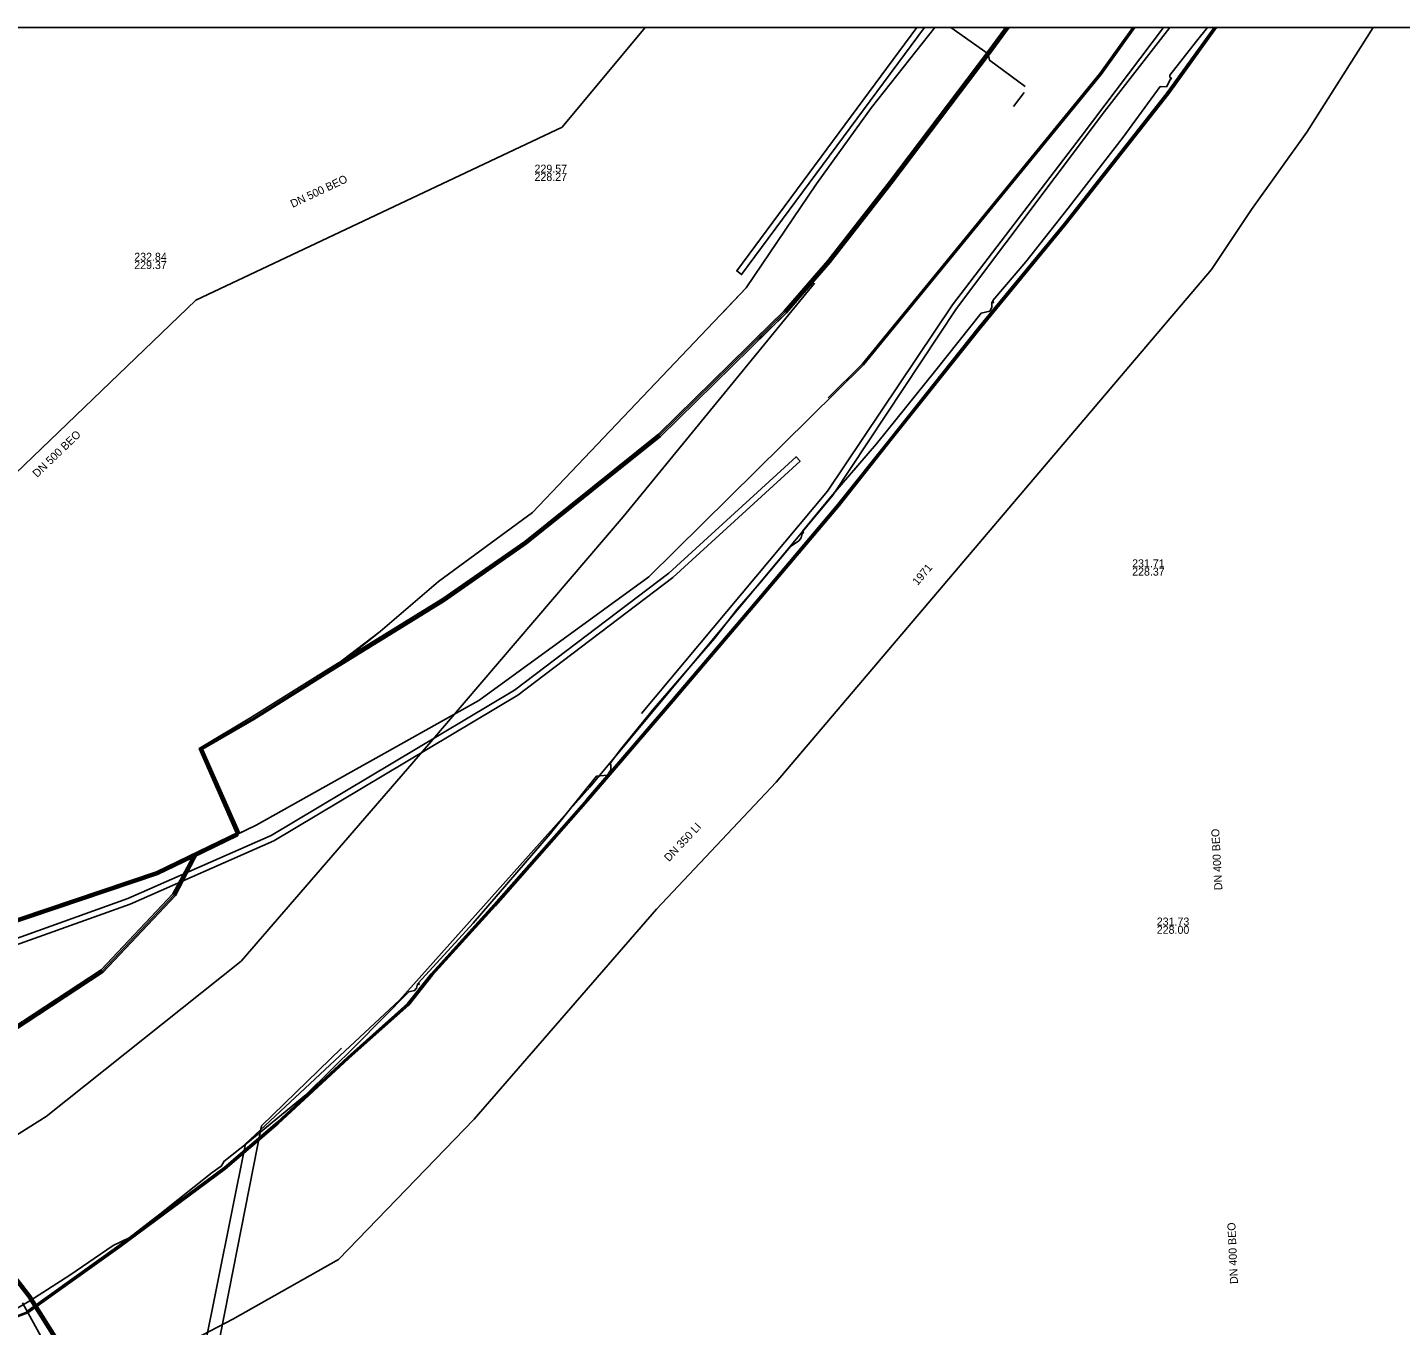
# Model space of a CAD drawing. Extents: x -599951 to -598963, y -1164095 to -1162939.
# Drawn here: x -599594.4 to -599456.3, y -1163069.9 to -1162939.4 of the extents above; entities that cross this region are included whole.
import ezdxf

# ---------------------------------------------------------------- set-up
doc = ezdxf.new("R2010")
doc.units = 0
for name, color, linetype in [('Level 3', 7, 'Continuous'), ('Vrstva 12', 7, 'Continuous'), ('Vrstva 13', 7, 'Continuous'), ('Vrstva 15', 7, 'Continuous'), ('Vrstva 20', 7, 'Continuous'), ('Vrstva 3', 7, 'Continuous'), ('Vrstva 42', 7, 'Continuous'), ('Vrstva 50', 7, 'Continuous'), ('Vrstva 53', 7, 'Continuous'), ('Vrstva 55', 7, 'Continuous'), ('Vrstva 58', 7, 'Continuous'), ('Vrstva 9', 7, 'Continuous')]:
    doc.layers.add(name, color=color, linetype=linetype)

msp = doc.modelspace()

# ---------------------------------------------------------------- linework, layer by layer
at = {"layer": 'Level 3'}
msp.add_lwpolyline([(-599584.11, -1163027.52), (-599598.37, -1163032.64), (-599613.87, -1163036.89), (-599614.07, -1163036.32), (-599598.55, -1163032.06), (-599584.33, -1163026.96), (-599569.91, -1163020.64), (-599545.43, -1163006.03), (-599529.92, -1162994.26), (-599517.12, -1162982.55), (-599516.72, -1162982.99), (-599529.52, -1162994.7), (-599545.1, -1163006.53), (-599569.63, -1163021.18)], close=True, dxfattribs=at)
at = {"layer": 'Vrstva 12'}
for points in [[(-599556.99, -1163037.17), (-599537.87, -1163015.77), (-599513.43, -1162986.4), (-599500.99, -1162967.66), (-599486.1, -1162947.86), (-599479.548, -1162939.4)], [(-599480.184, -1162939.4), (-599488.44, -1162950.37), (-599501.4, -1162967.28), (-599513.96, -1162986.01), (-599532.66, -1163008.37)], [(-599515.27, -1162965.1), (-599534.51, -1162988.59), (-599554.05, -1163011.44), (-599572.94, -1163033.27), (-599592.53, -1163048.89), (-599598.91, -1163052.86)], [(-599580.39, -1163090.87), (-599576.72, -1163072.64), (-599572.49, -1163051.64), (-599556.99, -1163037.17)], [(-599581.77, -1163105.29), (-599581.41, -1163103.32), (-599579.87, -1163095.47), (-599570.88, -1163049.8), (-599562.83, -1163042)]]:
    msp.add_lwpolyline(points, dxfattribs=at)
at = {"layer": 'Vrstva 13'}
msp.add_lwpolyline([(-599459.073, -1162939.4), (-599465.76, -1162949.91), (-599471.32, -1162957.71), (-599475.35, -1162963.72), (-599519.14, -1163015.26), (-599531.15, -1163028.03), (-599549.5, -1163049.13), (-599563.156, -1163063.255), (-599573.78, -1163069.24), (-599580.56, -1163072.79), (-599592.642, -1163078.384), (-599610.28, -1163084.85), (-599610.821, -1163085.298), (-599611.357, -1163087.777), (-599613.546, -1163097.928), (-599613.81, -1163099.161), (-599615.07, -1163098.93)], dxfattribs=at)
at = {"layer": 'Vrstva 20'}
msp.add_lwpolyline([(-599597.24, -1163069.57), (-599594.42, -1163068.52), (-599585.19, -1163061.92), (-599574.59, -1163054.08), (-599569.26, -1163049.53), (-599562.18, -1163042.98), (-599556.13, -1163037.6), (-599553.76, -1163034.6), (-599547.44, -1163027.63), (-599538.14, -1163017.07), (-599529.76, -1163007.34), (-599521.14, -1162997.21), (-599512.84, -1162987.4), (-599507.52, -1162980.7), (-599498.72, -1162969.67), (-599490.04, -1162959.12), (-599479.71, -1162946.01), (-599474.962, -1162939.4)], dxfattribs=at)
at = {"layer": 'Vrstva 3'}
msp.add_lwpolyline([(-599504.214, -1162939.4), (-599504.961, -1162939.4), (-599523.09, -1162963.88), (-599522.61, -1162964.24)], close=True, dxfattribs=at)
at = {"layer": 'Vrstva 42'}
msp.add_line((-599594.922, -1163067.606), (-599592.525, -1163071.983), dxfattribs=at)
msp.add_line((-599594.922, -1163067.606), (-599592.525, -1163071.983), dxfattribs=at)
for points in [[(-599749.027, -1163029.218), (-599735.259, -1163031.487), (-599723.979, -1163033.467), (-599712.924, -1163035.926), (-599705.328, -1163037.718), (-599700.258, -1163038.429), (-599690.404, -1163039.429), (-599677.558, -1163040.61), (-599659.147, -1163040.95), (-599646.467, -1163040.28), (-599632.098, -1163038.578), (-599618.469, -1163036.179), (-599614.518, -1163035.737), (-599581.333, -1163024.559), (-599577.857, -1163022.879), (-599573.291, -1163020.673), (-599573.217, -1163020.469), (-599571.42, -1163019.6), (-599549.04, -1163007.06), (-599531.92, -1162994.62), (-599510.34, -1162973.32), (-599486.45, -1162944.12), (-599483.06, -1162939.4)], [(-599749.027, -1163029.218), (-599735.259, -1163031.487), (-599723.979, -1163033.467), (-599712.924, -1163035.926), (-599705.328, -1163037.718), (-599700.258, -1163038.429), (-599690.404, -1163039.429), (-599677.558, -1163040.61), (-599659.147, -1163040.95), (-599646.467, -1163040.28), (-599632.098, -1163038.578), (-599618.469, -1163036.179), (-599614.518, -1163035.737), (-599581.333, -1163024.559), (-599577.857, -1163022.879), (-599573.291, -1163020.673), (-599573.217, -1163020.469), (-599571.42, -1163019.6), (-599549.04, -1163007.06), (-599531.92, -1162994.62), (-599510.34, -1162973.32), (-599486.45, -1162944.12), (-599483.06, -1162939.4)], [(-599503.151, -1162939.4), (-599509.52, -1162947.46), (-599515.08, -1162955.12), (-599522.14, -1162965.58), (-599543.62, -1162988.17), (-599553.09, -1162995.1), (-599558.94, -1163000.13), (-599564.205, -1163004.294), (-599571.652, -1163008.953), (-599576.813, -1163011.956), (-599573.142, -1163020.266), (-599577.232, -1163022.243), (-599581.447, -1163024.281), (-599614.582, -1163035.443), (-599614.666, -1163035.452), (-599624.359, -1163023.956), (-599624.638, -1163023.389)], [(-599503.151, -1162939.4), (-599509.52, -1162947.46), (-599515.08, -1162955.12), (-599522.14, -1162965.58), (-599543.62, -1162988.17), (-599553.09, -1162995.1), (-599558.94, -1163000.13), (-599564.205, -1163004.294), (-599571.652, -1163008.953), (-599576.812, -1163011.957), (-599573.142, -1163020.266), (-599577.232, -1163022.243), (-599581.447, -1163024.281), (-599614.582, -1163035.443), (-599614.666, -1163035.452), (-599624.359, -1163023.956), (-599624.638, -1163023.389)], [(-599614.582, -1163035.443), (-599581.447, -1163024.281), (-599577.232, -1163022.243), (-599573.142, -1163020.266), (-599576.812, -1163011.957), (-599571.652, -1163008.953), (-599564.205, -1163004.294), (-599552.478, -1162997.065), (-599544.22, -1162991.31), (-599530.77, -1162980.502), (-599518.101, -1162968.083), (-599513.704, -1162963.015), (-599507.501, -1162955.071), (-599497.689, -1162942.139), (-599495.705, -1162939.4)], [(-599495.705, -1162939.4), (-599497.689, -1162942.139), (-599507.501, -1162955.071), (-599513.704, -1162963.015), (-599518.101, -1162968.083), (-599530.77, -1162980.502), (-599544.22, -1162991.31), (-599552.478, -1162997.065), (-599564.205, -1163004.294), (-599571.652, -1163008.953), (-599576.813, -1163011.957), (-599573.142, -1163020.266), (-599577.232, -1163022.243), (-599581.447, -1163024.281), (-599614.582, -1163035.443)], [(-599614.55, -1163035.59), (-599581.39, -1163024.42), (-599571.42, -1163019.6), (-599549.04, -1163007.06), (-599531.92, -1162994.62), (-599510.34, -1162973.32), (-599486.45, -1162944.12), (-599483.06, -1162939.4)], [(-599496.076, -1162939.4), (-599497.931, -1162941.961), (-599507.739, -1162954.889), (-599513.936, -1162962.825), (-599518.319, -1162967.877), (-599530.97, -1162980.278), (-599544.4, -1162991.07), (-599552.642, -1162996.815), (-599564.375, -1163004.046), (-599571.888, -1163008.747), (-599577.147, -1163011.895), (-599573.292, -1163020.673), (-599577.857, -1163022.879), (-599579.797, -1163026.496), (-599587.017, -1163034.134), (-599595.986, -1163040.037)], [(-599496.076, -1162939.4), (-599497.931, -1162941.961), (-599507.739, -1162954.889), (-599513.936, -1162962.825), (-599518.319, -1162967.877), (-599530.97, -1162980.278), (-599544.4, -1162991.07), (-599552.642, -1162996.815), (-599564.375, -1163004.046), (-599571.888, -1163008.747), (-599577.147, -1163011.894), (-599573.292, -1163020.673), (-599577.857, -1163022.879), (-599579.797, -1163026.496), (-599587.017, -1163034.134), (-599595.986, -1163040.037)], [(-599503.151, -1162939.4), (-599509.52, -1162947.46), (-599515.08, -1162955.12), (-599522.14, -1162965.58), (-599543.62, -1162988.17), (-599553.09, -1162995.1), (-599558.94, -1163000.13), (-599564.205, -1163004.294), (-599571.652, -1163008.953), (-599576.812, -1163011.957), (-599573.142, -1163020.266), (-599577.232, -1163022.243), (-599579.543, -1163026.664), (-599586.823, -1163034.366), (-599595.814, -1163040.283)], [(-599503.151, -1162939.4), (-599509.52, -1162947.46), (-599515.08, -1162955.12), (-599522.14, -1162965.58), (-599543.62, -1162988.17), (-599553.09, -1162995.1), (-599558.94, -1163000.13), (-599564.205, -1163004.294), (-599571.652, -1163008.953), (-599576.813, -1163011.957), (-599573.142, -1163020.266), (-599577.232, -1163022.243), (-599579.543, -1163026.664), (-599586.823, -1163034.366), (-599595.814, -1163040.283)], [(-599564.29, -1163004.17), (-599558.94, -1163000.13), (-599553.09, -1162995.1), (-599543.62, -1162988.17), (-599522.14, -1162965.58), (-599515.08, -1162955.12), (-599509.52, -1162947.46), (-599503.151, -1162939.4)], [(-599495.89, -1162939.4), (-599497.81, -1162942.05), (-599507.62, -1162954.98), (-599513.82, -1162962.92), (-599518.21, -1162967.98), (-599530.87, -1162980.39), (-599544.31, -1162991.19), (-599552.56, -1162996.94), (-599564.29, -1163004.17)], [(-599524.464, -1162968.025), (-599522.14, -1162965.58), (-599515.08, -1162955.12), (-599509.52, -1162947.46), (-599503.151, -1162939.4)], [(-599496.076, -1162939.4), (-599497.931, -1162941.961), (-599507.739, -1162954.889), (-599513.936, -1162962.825), (-599518.319, -1162967.877), (-599521.192, -1162970.694)], [(-599495.705, -1162939.4), (-599497.689, -1162942.139), (-599507.501, -1162955.071), (-599513.704, -1162963.015), (-599518.101, -1162968.083), (-599520.959, -1162970.884)], [(-599513.91, -1162976.633), (-599510.451, -1162973.219), (-599486.569, -1162944.029), (-599483.245, -1162939.4)], [(-599501.551, -1162939.4), (-599497.81, -1162942.05), (-599497.66, -1162942.7), (-599494.092, -1162945.342)], [(-599494.092, -1162945.342), (-599497.66, -1162942.7), (-599497.81, -1162942.05), (-599501.551, -1162939.4)], [(-599497.81, -1162942.05), (-599497.66, -1162942.7), (-599494.092, -1162945.342)], [(-599497.766, -1162942.241), (-599497.66, -1162942.7), (-599494.092, -1162945.342)], [(-599494.178, -1162945.924), (-599495.24, -1162947.36)], [(-599494.178, -1162945.924), (-599495.24, -1162947.36)], [(-599494.178, -1162945.924), (-599495.24, -1162947.36)], [(-599494.178, -1162945.924), (-599495.24, -1162947.36)], [(-599609.94, -1163050.49), (-599595.9, -1163040.16), (-599586.92, -1163034.25), (-599579.67, -1163026.58), (-599577.539, -1163022.558), (-599573.217, -1163020.469), (-599576.974, -1163011.929), (-599571.77, -1163008.85), (-599564.29, -1163004.17)], [(-599614.253, -1163036.379), (-599613.969, -1163039.257), (-599613.476, -1163042.971), (-599610.073, -1163050.561), (-599606.969, -1163055.553), (-599606.712, -1163055.95), (-599600.533, -1163061.628), (-599596.394, -1163064.401), (-599594.353, -1163067.026), (-599588.255, -1163076.753), (-599585.176, -1163081.181), (-599582.184, -1163086.128), (-599581.12, -1163088.698), (-599577.553, -1163093.035), (-599566.411, -1163095.447), (-599558.51, -1163097.067), (-599539.961, -1163100.987), (-599528.61, -1163103.457), (-599512.094, -1163106.568), (-599502.939, -1163107.837), (-599495.901, -1163109.627), (-599471.178, -1163113.807), (-599460.607, -1163116.007), (-599450.989, -1163117.617)], [(-599614.253, -1163036.379), (-599613.969, -1163039.257), (-599613.476, -1163042.971), (-599610.073, -1163050.561), (-599606.969, -1163055.553), (-599606.712, -1163055.95), (-599600.533, -1163061.628), (-599596.394, -1163064.401), (-599594.353, -1163067.026), (-599588.255, -1163076.753), (-599585.176, -1163081.181), (-599582.184, -1163086.128), (-599581.12, -1163088.698), (-599577.553, -1163093.035), (-599566.411, -1163095.447), (-599558.51, -1163097.067), (-599539.961, -1163100.987), (-599528.61, -1163103.457), (-599512.094, -1163106.568), (-599502.939, -1163107.837), (-599495.901, -1163109.627), (-599471.178, -1163113.807), (-599460.607, -1163116.007), (-599450.989, -1163117.617)], [(-599450.931, -1163117.323), (-599460.553, -1163115.713), (-599471.122, -1163113.513), (-599495.839, -1163109.333), (-599502.881, -1163107.543), (-599512.046, -1163106.272), (-599528.55, -1163103.163), (-599539.899, -1163100.693), (-599558.45, -1163096.773), (-599566.349, -1163095.153), (-599577.387, -1163092.765), (-599580.86, -1163088.542), (-599581.916, -1163085.992), (-599584.924, -1163081.019), (-599588.005, -1163076.587), (-599594.107, -1163066.854), (-599596.186, -1163064.179)], [(-599450.931, -1163117.323), (-599460.553, -1163115.713), (-599471.122, -1163113.513), (-599495.839, -1163109.333), (-599502.881, -1163107.543), (-599512.046, -1163106.272), (-599528.55, -1163103.163), (-599539.899, -1163100.693), (-599558.45, -1163096.773), (-599566.349, -1163095.153), (-599577.387, -1163092.765), (-599580.86, -1163088.542), (-599581.916, -1163085.992), (-599584.924, -1163081.019), (-599588.005, -1163076.587), (-599594.107, -1163066.854), (-599596.186, -1163064.179)], [(-599596.186, -1163064.179), (-599594.107, -1163066.854), (-599588.005, -1163076.587), (-599584.924, -1163081.019), (-599581.916, -1163085.992), (-599580.86, -1163088.542), (-599577.387, -1163092.765), (-599566.349, -1163095.153), (-599558.45, -1163096.773), (-599539.899, -1163100.693), (-599528.55, -1163103.163), (-599512.046, -1163106.272), (-599502.881, -1163107.543), (-599495.839, -1163109.333), (-599471.122, -1163113.513), (-599460.553, -1163115.713), (-599450.931, -1163117.323)], [(-599596.186, -1163064.179), (-599594.107, -1163066.854), (-599588.005, -1163076.587), (-599584.924, -1163081.019), (-599581.916, -1163085.992), (-599580.86, -1163088.542), (-599577.387, -1163092.765), (-599566.349, -1163095.153), (-599558.45, -1163096.773), (-599539.899, -1163100.693), (-599528.55, -1163103.163), (-599512.046, -1163106.272), (-599502.881, -1163107.543), (-599495.839, -1163109.333), (-599471.122, -1163113.513), (-599460.553, -1163115.713), (-599450.931, -1163117.323)], [(-599596.29, -1163064.29), (-599594.23, -1163066.94), (-599588.13, -1163076.67), (-599585.05, -1163081.101), (-599582.05, -1163086.06), (-599580.99, -1163088.62), (-599577.47, -1163092.901), (-599566.38, -1163095.3), (-599558.481, -1163096.92), (-599539.93, -1163100.84), (-599528.58, -1163103.31), (-599512.07, -1163106.42), (-599502.91, -1163107.69), (-599495.87, -1163109.48), (-599471.15, -1163113.66), (-599460.581, -1163115.86), (-599450.96, -1163117.47)]]:
    msp.add_lwpolyline(points, dxfattribs=at)
at = {"layer": 'Vrstva 50'}
for points in [[(-599474.962, -1162939.4), (-599479.71, -1162946.01), (-599490.04, -1162959.12), (-599498.72, -1162969.67), (-599507.52, -1162980.7), (-599512.84, -1162987.4), (-599521.14, -1162997.21), (-599529.76, -1163007.34), (-599538.14, -1163017.07), (-599547.44, -1163027.63), (-599553.76, -1163034.6), (-599556.13, -1163037.6), (-599562.18, -1163042.98), (-599569.26, -1163049.53), (-599574.59, -1163054.08), (-599585.19, -1163061.92), (-599594.42, -1163068.52)], [(-599594.403, -1163068.513), (-599597.24, -1163069.57)]]:
    msp.add_lwpolyline(points, dxfattribs=at)
at = {"layer": 'Vrstva 53'}
msp.add_lwpolyline([(-599951.125, -1164094.695), (-598963.215, -1164094.695), (-598963.215, -1162939.4), (-599951.125, -1162939.4)], close=True, dxfattribs=at)
at = {"layer": 'Vrstva 55'}
msp.add_lwpolyline([(-599475.755, -1162939.4), (-599476.84, -1162940.79), (-599479.53, -1162944.2), (-599479.52, -1162944.426), (-599479.37, -1162944.49), (-599479.51, -1162944.66), (-599479.88, -1162945.37), (-599480.49, -1162945.34), (-599484.23, -1162950.44), (-599489.75, -1162957.58), (-599494.03, -1162962.95), (-599497.32, -1162966.856), (-599497.27, -1162967.07), (-599497.45, -1162967.01), (-599497.44, -1162967.54), (-599497.64, -1162967.91), (-599498.52, -1162968.12), (-599503.07, -1162973.85), (-599509.05, -1162981.24), (-599513.61, -1162986.57), (-599516.45, -1162990), (-599516.39, -1162990.2), (-599516.514, -1162990.263), (-599516.62, -1162990.7), (-599516.85, -1162991.01), (-599517.69, -1162991.59), (-599520.79, -1162995.31), (-599523.04, -1162997.89), (-599525.34, -1163000.82), (-599531.38, -1163007.82), (-599534.77, -1163011.99), (-599535.76, -1163013.28), (-599535.82, -1163013.41), (-599535.76, -1163013.538), (-599535.76, -1163014.04), (-599536.08, -1163014.57), (-599537.21, -1163014.68), (-599541.87, -1163020.47), (-599549.61, -1163029.44), (-599555.092, -1163035.441), (-599555.04, -1163035.61), (-599555.21, -1163035.57), (-599555.29, -1163035.98), (-599555.49, -1163036.22), (-599556.08, -1163036.33), (-599561.41, -1163041.73), (-599566.42, -1163046.71), (-599572.26, -1163051.5), (-599574.69, -1163053.39), (-599574.71, -1163053.5), (-599574.94, -1163053.88), (-599575.84, -1163054.49), (-599581.11, -1163058.7), (-599584.18, -1163061.09), (-599585.81, -1163061.86), (-599590.15, -1163064.83), (-599594.19, -1163067.42), (-599596.59, -1163068.81)], dxfattribs=at)
at = {"layer": 'Vrstva 58'}
for points in [[(-599597.194, -1163069.66), (-599594.373, -1163068.609), (-599585.131, -1163062.001), (-599574.528, -1163054.158), (-599569.194, -1163049.605), (-599562.113, -1163043.054), (-599556.057, -1163037.669), (-599553.684, -1163034.665), (-599547.365, -1163027.697), (-599538.065, -1163017.136), (-599529.684, -1163007.405), (-599521.064, -1162997.275), (-599512.763, -1162987.463), (-599507.442, -1162980.762), (-599498.642, -1162969.733), (-599489.962, -1162959.183), (-599479.63, -1162946.07), (-599474.839, -1162939.4)], [(-599597.194, -1163069.66), (-599594.373, -1163068.609), (-599585.131, -1163062.001), (-599574.528, -1163054.158), (-599569.194, -1163049.605), (-599562.113, -1163043.054), (-599556.057, -1163037.669), (-599553.684, -1163034.665), (-599547.365, -1163027.697), (-599538.065, -1163017.136), (-599529.684, -1163007.405), (-599521.064, -1162997.275), (-599512.763, -1162987.463), (-599507.442, -1162980.762), (-599498.642, -1162969.733), (-599489.962, -1162959.183), (-599479.63, -1162946.07), (-599474.839, -1162939.4)], [(-599594.467, -1163068.431), (-599585.249, -1163061.839), (-599574.652, -1163054.002), (-599569.326, -1163049.455), (-599562.247, -1163042.906), (-599556.203, -1163037.531), (-599553.836, -1163034.535), (-599547.515, -1163027.563), (-599538.215, -1163017.004), (-599529.836, -1163007.275), (-599521.216, -1162997.145), (-599512.917, -1162987.337), (-599507.598, -1162980.638), (-599498.798, -1162969.607), (-599490.118, -1162959.057), (-599479.79, -1162945.95), (-599475.085, -1162939.4)], [(-599594.42, -1163068.52), (-599585.19, -1163061.92), (-599574.59, -1163054.08), (-599569.26, -1163049.53), (-599562.18, -1163042.98), (-599556.13, -1163037.6), (-599553.76, -1163034.6), (-599547.44, -1163027.63), (-599538.14, -1163017.07), (-599529.76, -1163007.34), (-599521.14, -1162997.21), (-599512.84, -1162987.4), (-599507.52, -1162980.7), (-599498.72, -1162969.67), (-599490.04, -1162959.12), (-599479.71, -1162946.01), (-599474.962, -1162939.4)], [(-599594.42, -1163068.52), (-599585.19, -1163061.92), (-599574.59, -1163054.08), (-599569.26, -1163049.53), (-599562.18, -1163042.98), (-599556.13, -1163037.6), (-599553.76, -1163034.6), (-599547.44, -1163027.63), (-599538.14, -1163017.07), (-599529.76, -1163007.34), (-599521.14, -1162997.21), (-599512.84, -1162987.4), (-599507.52, -1162980.7), (-599498.72, -1162969.67), (-599490.04, -1162959.12), (-599479.71, -1162946.01), (-599474.962, -1162939.4)], [(-599594.42, -1163068.52), (-599585.19, -1163061.92), (-599574.59, -1163054.08), (-599569.26, -1163049.53), (-599562.18, -1163042.98), (-599556.13, -1163037.6), (-599553.76, -1163034.6), (-599547.44, -1163027.63), (-599538.14, -1163017.07), (-599529.76, -1163007.34), (-599521.14, -1162997.21), (-599512.84, -1162987.4), (-599507.52, -1162980.7), (-599498.72, -1162969.67), (-599490.04, -1162959.12), (-599479.71, -1162946.01), (-599474.962, -1162939.4)], [(-599594.42, -1163068.52), (-599585.19, -1163061.92), (-599574.59, -1163054.08), (-599569.26, -1163049.53), (-599562.18, -1163042.98), (-599556.13, -1163037.6), (-599553.76, -1163034.6), (-599547.44, -1163027.63), (-599538.14, -1163017.07), (-599529.76, -1163007.34), (-599521.14, -1162997.21), (-599512.84, -1162987.4), (-599507.52, -1162980.7), (-599498.72, -1162969.67), (-599490.04, -1162959.12), (-599479.71, -1162946.01), (-599474.962, -1162939.4)], [(-599594.42, -1163068.52), (-599585.19, -1163061.92), (-599574.59, -1163054.08), (-599569.26, -1163049.53), (-599562.18, -1163042.98), (-599556.13, -1163037.6), (-599553.76, -1163034.6), (-599547.44, -1163027.63), (-599538.14, -1163017.07), (-599529.76, -1163007.34), (-599521.14, -1162997.21), (-599512.84, -1162987.4), (-599507.52, -1162980.7), (-599498.72, -1162969.67), (-599490.04, -1162959.12), (-599479.71, -1162946.01), (-599474.962, -1162939.4)], [(-599594.42, -1163068.52), (-599585.19, -1163061.92), (-599574.59, -1163054.08), (-599569.26, -1163049.53), (-599562.18, -1163042.98), (-599556.13, -1163037.6), (-599553.76, -1163034.6), (-599547.44, -1163027.63), (-599538.14, -1163017.07), (-599529.76, -1163007.34), (-599521.14, -1162997.21), (-599512.84, -1162987.4), (-599507.52, -1162980.7), (-599498.72, -1162969.67), (-599490.04, -1162959.12), (-599479.71, -1162946.01), (-599474.962, -1162939.4)], [(-599594.383, -1163068.513), (-599597.24, -1163069.57), (-599599.57, -1163071.13), (-599603.92, -1163073.29), (-599612.56, -1163076.48), (-599624.49, -1163081.4), (-599626.27, -1163082.43), (-599627.09, -1163083.57), (-599627.23, -1163084.67), (-599627.64, -1163085), (-599628.33, -1163084.93), (-599658.24, -1163075.53), (-599659.28, -1163074.73), (-599660.66, -1163074.4), (-599661.91, -1163074.71), (-599663.05, -1163075.2), (-599663.79, -1163075.59), (-599681.39, -1163072.5), (-599685.12, -1163069.63), (-599711.66, -1163064.47), (-599725.02, -1163061.91), (-599736.37, -1163059.77), (-599740.93, -1163058.73), (-599749, -1163058.61)]]:
    msp.add_lwpolyline(points, dxfattribs=at)
at = {"layer": 'Vrstva 9'}
for p, q in [((-599540.658, -1162949.413), (-599532.296, -1162939.4)), ((-599577.497, -1162966.815), (-599540.658, -1162949.413))]:
    msp.add_line(p, q, dxfattribs=at)
msp.add_lwpolyline([(-599613.302, -1162995.258), (-599608.588, -1162994.579), (-599603.396, -1162991.687), (-599577.497, -1162966.815)], dxfattribs=at)

# ---------------------------------------------------------------- texts
at = {"layer": 'Vrstva 12'}
for s, p in [('229.57', (-599543.427, -1162953.991)), ('228.27', (-599543.427, -1162954.823)), ('232.84', (-599583.685, -1162962.851)), ('229.37', (-599583.685, -1162963.683)), ('231.71', (-599483.323, -1162993.669)), ('228.37', (-599483.323, -1162994.501)), ('231.73', (-599480.847, -1163029.677)), ('228.00', (-599480.847, -1163030.509))]:
    msp.add_text(s, height=0.8, dxfattribs=at).set_placement(p)
for s, rotation, p in [('DN 500 BEO', 25.28511, (-599567.749, -1162957.544)), ('DN 500 BEO', 43.84062, (-599593.446, -1162984.689)), ('DN 400 BEO', 92.99105, (-599474.25, -1163026.104)), ('DN 400 BEO', 92.53268, (-599472.676, -1163065.692))]:
    msp.add_text(s, height=0.8, rotation=rotation, dxfattribs=at).set_placement(p)
at = {"layer": 'Vrstva 15'}
for s, rotation, p in [('1971', 49.67544, (-599504.894, -1162995.546)), ('DN 350 LI', 46.75336, (-599529.901, -1163023.31))]:
    msp.add_text(s, height=0.8, rotation=rotation, dxfattribs=at).set_placement(p)

doc.saveas('drawing.dxf')
